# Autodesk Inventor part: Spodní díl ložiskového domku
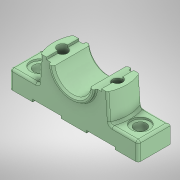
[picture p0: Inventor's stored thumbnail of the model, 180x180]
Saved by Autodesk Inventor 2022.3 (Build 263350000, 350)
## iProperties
Created: 2025-11
Part Number: Spodní díl ložiskového domku
Material: Všeobecné
Document SubType Name: Modeling
Designer: Hra42
Density: 1 g/cm^3
Appearance: Výchozí
Author: Hra42
Sending System: SolidWorks 2012
Last Author: Hra42
Last Saved: 2025-11-14
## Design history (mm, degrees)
feature "T_X2_011B_X0_leso1"
node "Těleso1"
